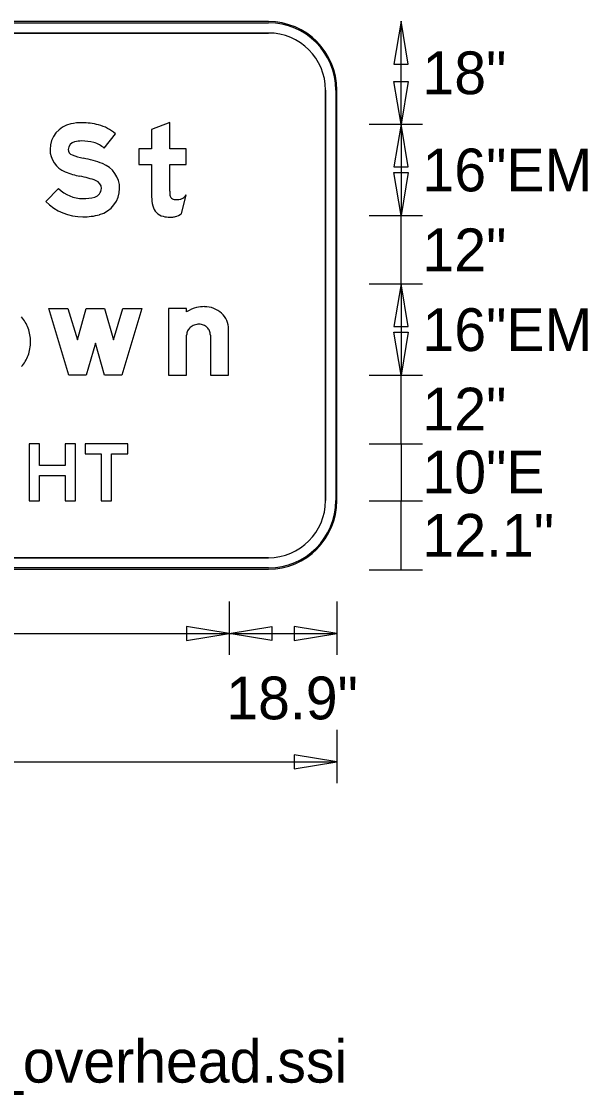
# Model space of a CAD drawing. Extents: x 1806251 to 1809821, y 414895 to 422886.
# Drawn here: x 1809677.853 to 1809678.845, y 414920.978 to 414922.862 of the extents above; entities that cross this region are included whole.
import ezdxf

# ---------------------------------------------------------------- set-up
doc = ezdxf.new("R2010")
doc.units = 0
for name, color, linetype in [('GSBWFILL', 7, 'Continuous'), ('GSCOLORFILL', 7, 'Continuous'), ('GSDIMS', 7, 'Continuous'), ('GSOUTLINE', 7, 'Continuous')]:
    doc.layers.add(name, color=color, linetype=linetype)

msp = doc.modelspace()

# ---------------------------------------------------------------- linework, layer by layer
at = {"layer": 'GSBWFILL'}
for p, q in [((1809678.286, 414922.8615), (1809676.905, 414922.8615)), ((1809676.905, 414922.8415), (1809678.286, 414922.8415)), ((1809678.386, 414922.7415), (1809678.386, 414922.0215)), ((1809678.406, 414922.0215), (1809678.406, 414922.7415)), ((1809678.1335, 414922.5246), (1809678.1419, 414922.5578)), ((1809678.1841, 414922.3118), (1809678.1841, 414922.2417)), ((1809678.286, 414921.9215), (1809676.9052, 414921.9215)), ((1809676.9052, 414921.9015), (1809678.286, 414921.9015))]:
    msp.add_line(p, q, dxfattribs=at)
for points in [[(1809678.1131, 414922.5641), (1809678.1131, 414922.6109), (1809678.1419, 414922.6109), (1809678.1419, 414922.6385), (1809678.1131, 414922.6385), (1809678.1131, 414922.6845), (1809678.0811, 414922.6723), (1809678.0811, 414922.6385), (1809678.0587, 414922.6385), (1809678.0587, 414922.6109), (1809678.0811, 414922.6109), (1809678.0811, 414922.5544)], [(1809677.9979, 414922.6394), (1809678.0177, 414922.6647)], [(1809677.918, 414922.5687), (1809677.8955, 414922.546)], [(1809678.1425, 414922.3527), (1809678.1425, 414922.3585), (1809678.1105, 414922.3585), (1809678.1105, 414922.2417), (1809678.1425, 414922.2417), (1809678.1425, 414922.3118)], [(1809678.1841, 414922.2417), (1809678.2161, 414922.2417), (1809678.2161, 414922.3224)]]:
    msp.add_lwpolyline(points, dxfattribs=at)
for points in [[(1809678.0641, 414922.3585), (1809678.0289, 414922.2417), (1809677.9985, 414922.2417), (1809677.9825, 414922.2977), (1809677.9665, 414922.2417), (1809677.9361, 414922.2417), (1809677.9009, 414922.3585), (1809677.9343, 414922.3585), (1809677.9509, 414922.3035), (1809677.9666, 414922.3585), (1809677.9984, 414922.3585), (1809678.0141, 414922.3035), (1809678.0307, 414922.3585)], [(1809677.9294, 414922.0833), (1809677.8844, 414922.0833), (1809677.8844, 414922.1213), (1809677.8664, 414922.1213), (1809677.8664, 414922.0213), (1809677.8844, 414922.0213), (1809677.8844, 414922.0653), (1809677.9294, 414922.0653), (1809677.9294, 414922.0213), (1809677.9474, 414922.0213), (1809677.9474, 414922.1213), (1809677.9294, 414922.1213)], [(1809677.9644, 414922.1033), (1809677.9929, 414922.1033), (1809677.9929, 414922.0213), (1809678.0109, 414922.0213), (1809678.0109, 414922.1033), (1809678.0394, 414922.1033), (1809678.0394, 414922.1213), (1809677.9644, 414922.1213)]]:
    msp.add_lwpolyline(points, close=True, dxfattribs=at)
for centre, radius, start, end in [((1809678.286, 414922.7415), 0.12, 0, 90), ((1809678.286, 414922.7415), 0.1, 0, 90), ((1809678.286, 414922.0215), 0.12, 270, 0), ((1809678.286, 414922.0215), 0.1, 270, 0)]:
    msp.add_arc(centre, radius, start, end, dxfattribs=at)
for centre, major_axis, ratio, start_param, end_param in [((1809677.9489, 414922.6374), (0, 0.0458), 0.999997, 0.202758, 1.570796), ((1809677.9587, 414922.5899), (0, 0.0943), 0.999997, 0, 0.202758), ((1809677.9587, 414922.5686), (0, 0.1156), 0.999997, 6.026234, 6.283185), ((1809677.9694, 414922.6094), (0, 0.0734), 0.999997, 5.565152, 6.026234), ((1809677.9489, 414922.6374), (0, 0.0138), 0.999997, 0.202758, 1.570796), ((1809677.9587, 414922.5899), (0, 0.0623), 0.999997, 0, 0.202758), ((1809677.9587, 414922.5686), (0, 0.0836), 0.999997, 6.026234, 6.283185), ((1809677.9694, 414922.6094), (0, 0.0414), 0.999997, 5.523837, 6.026234), ((1809677.9455, 414922.6374), (0, 0.0425), 0.999997, 1.570796, 2.761249), ((1809677.9455, 414922.6374), (0, 0.0105), 0.999997, 1.570796, 2.761249), ((1809677.9804, 414922.7246), (0, 0.1044), 0.999997, 2.761249, 2.95744), ((1809677.9256, 414922.4304), (0, 0.1948), 0.999997, 5.918637, 6.099033), ((1809677.9785, 414922.5689), (0, 0.0466), 0.999997, 4.712389, 5.918637), ((1809677.9804, 414922.7246), (0, 0.1364), 0.999997, 2.761249, 2.95744), ((1809677.9256, 414922.4304), (0, 0.1628), 0.999997, 5.918637, 6.099033), ((1809677.9785, 414922.5689), (0, 0.0146), 0.999997, 4.712389, 5.918637), ((1809677.9606, 414922.6117), (0, 0.0605), 0.999997, 2.360607, 3.141593), ((1809677.9775, 414922.5689), (0, 0.0155), 0.999997, 3.401517, 4.712389), ((1809677.9775, 414922.5689), (0, 0.0475), 0.999997, 3.401517, 4.712389), ((1809678.3134, 414922.5641), (0, 0.2003), 0.999998, 1.570796, 1.606005), ((1809677.9606, 414922.6117), (0, 0.0925), 0.999997, 2.360607, 3.141593), ((1809677.9606, 414922.6325), (0, 0.0814), 0.999997, 3.141593, 3.401517), ((1809678.1432, 414922.5544), (0, 0.0621), 0.999998, 1.570796, 1.830698), ((1809678.1223, 414922.5586), (0, 0.0092), 0.999998, 1.74085, 2.407828), ((1809678.1226, 414922.5589), (0, 0.00963), 0.999998, 2.407828, 3.141593), ((1809678.1226, 414922.5998), (0, 0.0505), 0.999998, 3.141593, 3.310762), ((1809678.129, 414922.5618), (0, 0.012), 0.999998, 3.310762, 3.756278), ((1809678.1208, 414922.5735), (0, 0.0263), 0.999998, 3.756278, 4.071638), ((1809678.1083, 414922.5451), (0, 0.026), 0.999998, 1.830698, 2.869526), ((1809677.9606, 414922.6325), (0, 0.1134), 0.999997, 3.141593, 3.401517), ((1809678.1131, 414922.5623), (0, 0.0438), 0.999998, 2.869526, 3.141593), ((1809678.1131, 414922.5816), (0, 0.0631), 0.999998, 3.141593, 3.205734), ((1809678.1155, 414922.5445), (0, 0.026), 0.999998, 3.205734, 3.427755), ((1809678.112, 414922.5561), (0, 0.0381), 0.999998, 3.427755, 3.738844), ((1809678.1735, 414922.3041), (0, 0.0576), 0.999997, 0.235088, 0.567132), ((1809678.174, 414922.2977), (0, 0.064), 0.999997, 0, 0.219986), ((1809678.174, 414922.3166), (0, 0.045), 0.999997, 5.914285, 6.283185), ((1809678.1751, 414922.3194), (0, 0.042), 0.999997, 5.532258, 5.914285), ((1809677.8067, 414922.3028), (0, 0.0617), 0.999994, 5.063069, 5.435798), ((1809678.1768, 414922.3212), (0, 0.0396), 0.999997, 5.130076, 5.532258), ((1809677.7993, 414922.3001), (0, 0.0696), 0.999994, 4.712389, 5.063069), ((1809678.1592, 414922.3118), (0, 0.0167), 0.999997, 1.126231, 1.570796), ((1809678.1617, 414922.3106), (0, 0.0195), 0.999997, 0.715718, 1.126231), ((1809678.1634, 414922.3087), (0, 0.022), 0.999997, 0.345704, 0.715718), ((1809678.1645, 414922.3057), (0, 0.0252), 0.999997, 0, 0.345704), ((1809678.1645, 414922.3107), (0, 0.0202), 0.999997, 5.900624, 6.283185), ((1809678.1647, 414922.3113), (0, 0.0196), 0.999997, 5.51227, 5.900624), ((1809678.165, 414922.3116), (0, 0.0191), 0.999997, 5.115435, 5.51227), ((1809678.1655, 414922.3118), (0, 0.0186), 0.999997, 4.712389, 5.115435), ((1809678.1794, 414922.3224), (0, 0.0367), 0.999997, 4.712389, 5.130076), ((1809677.7993, 414922.3001), (0, 0.0696), 0.999994, 4.361709, 4.712389), ((1809677.8067, 414922.2973), (0, 0.0617), 0.999994, 3.98898, 4.361709)]:
    msp.add_ellipse(centre, major_axis=major_axis, ratio=ratio, start_param=start_param, end_param=end_param, dxfattribs=at)
at = {"layer": 'GSCOLORFILL'}
for p, q in [((1809678.286, 414922.8615), (1809676.905, 414922.8615)), ((1809678.286, 414922.8615), (1809676.905, 414922.8615)), ((1809678.286, 414922.8615), (1809676.905, 414922.8615)), ((1809676.905, 414922.8595), (1809678.286, 414922.8595)), ((1809676.905, 414922.8415), (1809678.286, 414922.8415)), ((1809678.386, 414922.7415), (1809678.386, 414922.0215)), ((1809678.404, 414922.7415), (1809678.404, 414922.0215)), ((1809678.406, 414922.0215), (1809678.406, 414922.7415)), ((1809678.406, 414922.0215), (1809678.406, 414922.7415)), ((1809678.406, 414922.0215), (1809678.406, 414922.7415)), ((1809678.1335, 414922.5246), (1809678.1419, 414922.5578)), ((1809678.1841, 414922.3118), (1809678.1841, 414922.2417)), ((1809678.286, 414921.9215), (1809676.9052, 414921.9215)), ((1809678.286, 414921.9035), (1809676.905, 414921.9035)), ((1809676.905, 414921.9015), (1809678.286, 414921.9015)), ((1809676.905, 414921.9015), (1809678.286, 414921.9015)), ((1809676.9052, 414921.9015), (1809678.286, 414921.9015))]:
    msp.add_line(p, q, dxfattribs=at)
for points in [[(1809678.1131, 414922.5641), (1809678.1131, 414922.6109), (1809678.1419, 414922.6109), (1809678.1419, 414922.6385), (1809678.1131, 414922.6385), (1809678.1131, 414922.6845), (1809678.0811, 414922.6723), (1809678.0811, 414922.6385), (1809678.0587, 414922.6385), (1809678.0587, 414922.6109), (1809678.0811, 414922.6109), (1809678.0811, 414922.5544)], [(1809677.9979, 414922.6394), (1809678.0177, 414922.6647)], [(1809677.918, 414922.5687), (1809677.8955, 414922.546)], [(1809678.1425, 414922.3527), (1809678.1425, 414922.3585), (1809678.1105, 414922.3585), (1809678.1105, 414922.2417), (1809678.1425, 414922.2417), (1809678.1425, 414922.3118)], [(1809678.1841, 414922.2417), (1809678.2161, 414922.2417), (1809678.2161, 414922.3224)]]:
    msp.add_lwpolyline(points, dxfattribs=at)
for points in [[(1809678.0641, 414922.3585), (1809678.0289, 414922.2417), (1809677.9985, 414922.2417), (1809677.9825, 414922.2977), (1809677.9665, 414922.2417), (1809677.9361, 414922.2417), (1809677.9009, 414922.3585), (1809677.9343, 414922.3585), (1809677.9509, 414922.3035), (1809677.9666, 414922.3585), (1809677.9984, 414922.3585), (1809678.0141, 414922.3035), (1809678.0307, 414922.3585)], [(1809677.9294, 414922.0833), (1809677.8844, 414922.0833), (1809677.8844, 414922.1213), (1809677.8664, 414922.1213), (1809677.8664, 414922.0213), (1809677.8844, 414922.0213), (1809677.8844, 414922.0653), (1809677.9294, 414922.0653), (1809677.9294, 414922.0213), (1809677.9474, 414922.0213), (1809677.9474, 414922.1213), (1809677.9294, 414922.1213)], [(1809677.9644, 414922.1033), (1809677.9929, 414922.1033), (1809677.9929, 414922.0213), (1809678.0109, 414922.0213), (1809678.0109, 414922.1033), (1809678.0394, 414922.1033), (1809678.0394, 414922.1213), (1809677.9644, 414922.1213)]]:
    msp.add_lwpolyline(points, close=True, dxfattribs=at)
for centre, radius, start, end in [((1809678.286, 414922.7415), 0.12, 0, 90), ((1809678.286, 414922.7415), 0.12, 0, 90), ((1809678.286, 414922.7415), 0.12, 0, 90), ((1809678.286, 414922.7415), 0.118, 0, 90), ((1809678.286, 414922.7415), 0.1, 0, 90), ((1809678.286, 414922.0215), 0.12, 270, 0), ((1809678.286, 414922.0215), 0.12, 270, 0), ((1809678.286, 414922.0215), 0.1, 270, 0), ((1809678.286, 414922.0215), 0.12, 270, 0), ((1809678.286, 414922.0215), 0.118, 270, 0)]:
    msp.add_arc(centre, radius, start, end, dxfattribs=at)
for centre, major_axis, ratio, start_param, end_param in [((1809677.9489, 414922.6374), (0, 0.0458), 0.999997, 0.202758, 1.570796), ((1809677.9587, 414922.5899), (0, 0.0943), 0.999997, 0, 0.202758), ((1809677.9587, 414922.5686), (0, 0.1156), 0.999997, 6.026234, 6.283185), ((1809677.9694, 414922.6094), (0, 0.0734), 0.999997, 5.565152, 6.026234), ((1809677.9489, 414922.6374), (0, 0.0138), 0.999997, 0.202758, 1.570796), ((1809677.9587, 414922.5899), (0, 0.0623), 0.999997, 0, 0.202758), ((1809677.9587, 414922.5686), (0, 0.0836), 0.999997, 6.026234, 6.283185), ((1809677.9694, 414922.6094), (0, 0.0414), 0.999997, 5.523837, 6.026234), ((1809677.9455, 414922.6374), (0, 0.0425), 0.999997, 1.570796, 2.761249), ((1809677.9455, 414922.6374), (0, 0.0105), 0.999997, 1.570796, 2.761249), ((1809677.9804, 414922.7246), (0, 0.1044), 0.999997, 2.761249, 2.95744), ((1809677.9256, 414922.4304), (0, 0.1948), 0.999997, 5.918637, 6.099033), ((1809677.9785, 414922.5689), (0, 0.0466), 0.999997, 4.712389, 5.918637), ((1809677.9804, 414922.7246), (0, 0.1364), 0.999997, 2.761249, 2.95744), ((1809677.9256, 414922.4304), (0, 0.1628), 0.999997, 5.918637, 6.099033), ((1809677.9785, 414922.5689), (0, 0.0146), 0.999997, 4.712389, 5.918637), ((1809677.9606, 414922.6117), (0, 0.0605), 0.999997, 2.360607, 3.141593), ((1809677.9775, 414922.5689), (0, 0.0155), 0.999997, 3.401517, 4.712389), ((1809677.9775, 414922.5689), (0, 0.0475), 0.999997, 3.401517, 4.712389), ((1809678.3134, 414922.5641), (0, 0.2003), 0.999998, 1.570796, 1.606005), ((1809677.9606, 414922.6117), (0, 0.0925), 0.999997, 2.360607, 3.141593), ((1809677.9606, 414922.6325), (0, 0.0814), 0.999997, 3.141593, 3.401517), ((1809678.1432, 414922.5544), (0, 0.0621), 0.999998, 1.570796, 1.830698), ((1809678.1223, 414922.5586), (0, 0.0092), 0.999998, 1.74085, 2.407828), ((1809678.1226, 414922.5589), (0, 0.00963), 0.999998, 2.407828, 3.141593), ((1809678.1226, 414922.5998), (0, 0.0505), 0.999998, 3.141593, 3.310762), ((1809678.129, 414922.5618), (0, 0.012), 0.999998, 3.310762, 3.756278), ((1809678.1208, 414922.5735), (0, 0.0263), 0.999998, 3.756278, 4.071638), ((1809678.1083, 414922.5451), (0, 0.026), 0.999998, 1.830698, 2.869526), ((1809677.9606, 414922.6325), (0, 0.1134), 0.999997, 3.141593, 3.401517), ((1809678.1131, 414922.5623), (0, 0.0438), 0.999998, 2.869526, 3.141593), ((1809678.1131, 414922.5816), (0, 0.0631), 0.999998, 3.141593, 3.205734), ((1809678.1155, 414922.5445), (0, 0.026), 0.999998, 3.205734, 3.427755), ((1809678.112, 414922.5561), (0, 0.0381), 0.999998, 3.427755, 3.738844), ((1809678.1735, 414922.3041), (0, 0.0576), 0.999997, 0.235088, 0.567132), ((1809678.174, 414922.2977), (0, 0.064), 0.999997, 0, 0.219986), ((1809678.174, 414922.3166), (0, 0.045), 0.999997, 5.914285, 6.283185), ((1809678.1751, 414922.3194), (0, 0.042), 0.999997, 5.532258, 5.914285), ((1809677.8067, 414922.3028), (0, 0.0617), 0.999994, 5.063069, 5.435798), ((1809678.1768, 414922.3212), (0, 0.0396), 0.999997, 5.130076, 5.532258), ((1809677.7993, 414922.3001), (0, 0.0696), 0.999994, 4.712389, 5.063069), ((1809678.1592, 414922.3118), (0, 0.0167), 0.999997, 1.126231, 1.570796), ((1809678.1617, 414922.3106), (0, 0.0195), 0.999997, 0.715718, 1.126231), ((1809678.1634, 414922.3087), (0, 0.022), 0.999997, 0.345704, 0.715718), ((1809678.1645, 414922.3057), (0, 0.0252), 0.999997, 0, 0.345704), ((1809678.1645, 414922.3107), (0, 0.0202), 0.999997, 5.900624, 6.283185), ((1809678.1647, 414922.3113), (0, 0.0196), 0.999997, 5.51227, 5.900624), ((1809678.165, 414922.3116), (0, 0.0191), 0.999997, 5.115435, 5.51227), ((1809678.1655, 414922.3118), (0, 0.0186), 0.999997, 4.712389, 5.115435), ((1809678.1794, 414922.3224), (0, 0.0367), 0.999997, 4.712389, 5.130076), ((1809677.7993, 414922.3001), (0, 0.0696), 0.999994, 4.361709, 4.712389), ((1809677.8067, 414922.2973), (0, 0.0617), 0.999994, 3.98898, 4.361709)]:
    msp.add_ellipse(centre, major_axis=major_axis, ratio=ratio, start_param=start_param, end_param=end_param, dxfattribs=at)
at = {"layer": 'GSDIMS'}
for p, q in [((1809678.5185, 414922.6817), (1809678.5185, 414922.862)), ((1809678.4623, 414922.6817), (1809678.556, 414922.6817)), ((1809678.4623, 414922.6817), (1809678.556, 414922.6817)), ((1809678.5185, 414922.6817), (1809678.5185, 414922.5217)), ((1809678.4623, 414922.5217), (1809678.556, 414922.5217)), ((1809678.4623, 414922.5217), (1809678.556, 414922.5217)), ((1809678.5185, 414922.4017), (1809678.5185, 414922.5217)), ((1809678.4623, 414922.4017), (1809678.556, 414922.4017)), ((1809678.4623, 414922.4017), (1809678.556, 414922.4017)), ((1809678.5185, 414922.4017), (1809678.5185, 414922.2417)), ((1809678.4623, 414922.2417), (1809678.556, 414922.2417)), ((1809678.4623, 414922.2417), (1809678.556, 414922.2417)), ((1809678.5185, 414922.1213), (1809678.5185, 414922.2417)), ((1809678.4623, 414922.1213), (1809678.556, 414922.1213)), ((1809678.4623, 414922.1213), (1809678.556, 414922.1213)), ((1809678.5185, 414922.1213), (1809678.5185, 414922.0213)), ((1809678.4623, 414922.0213), (1809678.556, 414922.0213)), ((1809678.4623, 414922.0213), (1809678.556, 414922.0213)), ((1809678.5185, 414921.9003), (1809678.5185, 414922.0213)), ((1809678.4623, 414921.9003), (1809678.556, 414921.9003)), ((1809678.217, 414921.8447), (1809678.217, 414921.751)), ((1809678.217, 414921.8447), (1809678.217, 414921.751)), ((1809678.406, 414921.8447), (1809678.406, 414921.751)), ((1809676.9729, 414921.7885), (1809678.217, 414921.7885)), ((1809678.217, 414921.7885), (1809678.406, 414921.7885)), ((1809678.406, 414921.6198), (1809678.406, 414921.526)), ((1809676.785, 414921.5635), (1809678.406, 414921.5635))]:
    msp.add_line(p, q, dxfattribs=at)
for points in [[(1809678.5185, 414922.862), (1809678.506, 414922.787), (1809678.531, 414922.787)], [(1809678.5185, 414922.6817), (1809678.506, 414922.7567), (1809678.531, 414922.7567)], [(1809678.5185, 414922.6817), (1809678.506, 414922.6067), (1809678.531, 414922.6067)], [(1809678.5185, 414922.5217), (1809678.506, 414922.5967), (1809678.531, 414922.5967)], [(1809678.5185, 414922.4017), (1809678.506, 414922.3267), (1809678.531, 414922.3267)], [(1809678.5185, 414922.2417), (1809678.506, 414922.3167), (1809678.531, 414922.3167)], [(1809678.217, 414921.7885), (1809678.142, 414921.801), (1809678.142, 414921.776)], [(1809678.217, 414921.7885), (1809678.292, 414921.801), (1809678.292, 414921.776)], [(1809678.406, 414921.7885), (1809678.331, 414921.801), (1809678.331, 414921.776)], [(1809678.406, 414921.5635), (1809678.331, 414921.576), (1809678.331, 414921.551)]]:
    msp.add_lwpolyline(points, close=True, dxfattribs=at)
at = {"layer": 'GSOUTLINE'}
for p, q in [((1809678.286, 414922.8615), (1809676.905, 414922.8615)), ((1809678.286, 414922.8415), (1809676.905, 414922.8415)), ((1809678.386, 414922.0215), (1809678.386, 414922.7415)), ((1809678.406, 414922.0215), (1809678.406, 414922.7415)), ((1809678.1335, 414922.5246), (1809678.1419, 414922.5578)), ((1809678.1841, 414922.3118), (1809678.1841, 414922.2417)), ((1809676.905, 414921.9215), (1809678.286, 414921.9215)), ((1809676.905, 414921.9015), (1809678.286, 414921.9015))]:
    msp.add_line(p, q, dxfattribs=at)
for points in [[(1809678.1131, 414922.5641), (1809678.1131, 414922.6109), (1809678.1419, 414922.6109), (1809678.1419, 414922.6385), (1809678.1131, 414922.6385), (1809678.1131, 414922.6845), (1809678.0811, 414922.6723), (1809678.0811, 414922.6385), (1809678.0587, 414922.6385), (1809678.0587, 414922.6109), (1809678.0811, 414922.6109), (1809678.0811, 414922.5544)], [(1809677.9979, 414922.6394), (1809678.0177, 414922.6647)], [(1809677.918, 414922.5687), (1809677.8955, 414922.546)], [(1809678.1425, 414922.3527), (1809678.1425, 414922.3585), (1809678.1105, 414922.3585), (1809678.1105, 414922.2417), (1809678.1425, 414922.2417), (1809678.1425, 414922.3118)], [(1809678.1841, 414922.2417), (1809678.2161, 414922.2417), (1809678.2161, 414922.3224)]]:
    msp.add_lwpolyline(points, dxfattribs=at)
for points in [[(1809678.0641, 414922.3585), (1809678.0289, 414922.2417), (1809677.9985, 414922.2417), (1809677.9825, 414922.2977), (1809677.9665, 414922.2417), (1809677.9361, 414922.2417), (1809677.9009, 414922.3585), (1809677.9343, 414922.3585), (1809677.9509, 414922.3035), (1809677.9666, 414922.3585), (1809677.9984, 414922.3585), (1809678.0141, 414922.3035), (1809678.0307, 414922.3585)], [(1809677.9294, 414922.0833), (1809677.8844, 414922.0833), (1809677.8844, 414922.1213), (1809677.8664, 414922.1213), (1809677.8664, 414922.0213), (1809677.8844, 414922.0213), (1809677.8844, 414922.0653), (1809677.9294, 414922.0653), (1809677.9294, 414922.0213), (1809677.9474, 414922.0213), (1809677.9474, 414922.1213), (1809677.9294, 414922.1213)], [(1809677.9644, 414922.1033), (1809677.9929, 414922.1033), (1809677.9929, 414922.0213), (1809678.0109, 414922.0213), (1809678.0109, 414922.1033), (1809678.0394, 414922.1033), (1809678.0394, 414922.1213), (1809677.9644, 414922.1213)]]:
    msp.add_lwpolyline(points, close=True, dxfattribs=at)
for centre, radius, start, end in [((1809678.286, 414922.7415), 0.12, 0, 90), ((1809678.286, 414922.7415), 0.1, 0, 90), ((1809678.286, 414922.0215), 0.12, 270, 0), ((1809678.286, 414922.0215), 0.1, 270, 0)]:
    msp.add_arc(centre, radius, start, end, dxfattribs=at)
for centre, major_axis, ratio, start_param, end_param in [((1809677.9489, 414922.6374), (0, 0.0458), 0.999997, 0.202758, 1.570796), ((1809677.9587, 414922.5899), (0, 0.0943), 0.999997, 0, 0.202758), ((1809677.9587, 414922.5686), (0, 0.1156), 0.999997, 6.026234, 6.283185), ((1809677.9694, 414922.6094), (0, 0.0734), 0.999997, 5.565152, 6.026234), ((1809677.9489, 414922.6374), (0, 0.0138), 0.999997, 0.202758, 1.570796), ((1809677.9587, 414922.5899), (0, 0.0623), 0.999997, 0, 0.202758), ((1809677.9587, 414922.5686), (0, 0.0836), 0.999997, 6.026234, 6.283185), ((1809677.9694, 414922.6094), (0, 0.0414), 0.999997, 5.523837, 6.026234), ((1809677.9455, 414922.6374), (0, 0.0425), 0.999997, 1.570796, 2.761249), ((1809677.9455, 414922.6374), (0, 0.0105), 0.999997, 1.570796, 2.761249), ((1809677.9804, 414922.7246), (0, 0.1044), 0.999997, 2.761249, 2.95744), ((1809677.9256, 414922.4304), (0, 0.1948), 0.999997, 5.918637, 6.099033), ((1809677.9785, 414922.5689), (0, 0.0466), 0.999997, 4.712389, 5.918637), ((1809677.9804, 414922.7246), (0, 0.1364), 0.999997, 2.761249, 2.95744), ((1809677.9256, 414922.4304), (0, 0.1628), 0.999997, 5.918637, 6.099033), ((1809677.9785, 414922.5689), (0, 0.0146), 0.999997, 4.712389, 5.918637), ((1809677.9606, 414922.6117), (0, 0.0605), 0.999997, 2.360607, 3.141593), ((1809677.9775, 414922.5689), (0, 0.0155), 0.999997, 3.401517, 4.712389), ((1809677.9775, 414922.5689), (0, 0.0475), 0.999997, 3.401517, 4.712389), ((1809678.3134, 414922.5641), (0, 0.2003), 0.999998, 1.570796, 1.606005), ((1809677.9606, 414922.6117), (0, 0.0925), 0.999997, 2.360607, 3.141593), ((1809677.9606, 414922.6325), (0, 0.0814), 0.999997, 3.141593, 3.401517), ((1809678.1432, 414922.5544), (0, 0.0621), 0.999998, 1.570796, 1.830698), ((1809678.1223, 414922.5586), (0, 0.0092), 0.999998, 1.74085, 2.407828), ((1809678.1226, 414922.5589), (0, 0.00963), 0.999998, 2.407828, 3.141593), ((1809678.1226, 414922.5998), (0, 0.0505), 0.999998, 3.141593, 3.310762), ((1809678.129, 414922.5618), (0, 0.012), 0.999998, 3.310762, 3.756278), ((1809678.1208, 414922.5735), (0, 0.0263), 0.999998, 3.756278, 4.071638), ((1809678.1083, 414922.5451), (0, 0.026), 0.999998, 1.830698, 2.869526), ((1809677.9606, 414922.6325), (0, 0.1134), 0.999997, 3.141593, 3.401517), ((1809678.1131, 414922.5623), (0, 0.0438), 0.999998, 2.869526, 3.141593), ((1809678.1131, 414922.5816), (0, 0.0631), 0.999998, 3.141593, 3.205734), ((1809678.1155, 414922.5445), (0, 0.026), 0.999998, 3.205734, 3.427755), ((1809678.112, 414922.5561), (0, 0.0381), 0.999998, 3.427755, 3.738844), ((1809678.1735, 414922.3041), (0, 0.0576), 0.999997, 0.235088, 0.567132), ((1809678.174, 414922.2977), (0, 0.064), 0.999997, 0, 0.219986), ((1809678.174, 414922.3166), (0, 0.045), 0.999997, 5.914285, 6.283185), ((1809678.1751, 414922.3194), (0, 0.042), 0.999997, 5.532258, 5.914285), ((1809677.8067, 414922.3028), (0, 0.0617), 0.999994, 5.063069, 5.435798), ((1809678.1768, 414922.3212), (0, 0.0396), 0.999997, 5.130076, 5.532258), ((1809677.7993, 414922.3001), (0, 0.0696), 0.999994, 4.712389, 5.063069), ((1809678.1592, 414922.3118), (0, 0.0167), 0.999997, 1.126231, 1.570796), ((1809678.1617, 414922.3106), (0, 0.0195), 0.999997, 0.715718, 1.126231), ((1809678.1634, 414922.3087), (0, 0.022), 0.999997, 0.345704, 0.715718), ((1809678.1645, 414922.3057), (0, 0.0252), 0.999997, 0, 0.345704), ((1809678.1645, 414922.3107), (0, 0.0202), 0.999997, 5.900624, 6.283185), ((1809678.1647, 414922.3113), (0, 0.0196), 0.999997, 5.51227, 5.900624), ((1809678.165, 414922.3116), (0, 0.0191), 0.999997, 5.115435, 5.51227), ((1809678.1655, 414922.3118), (0, 0.0186), 0.999997, 4.712389, 5.115435), ((1809678.1794, 414922.3224), (0, 0.0367), 0.999997, 4.712389, 5.130076), ((1809677.7993, 414922.3001), (0, 0.0696), 0.999994, 4.361709, 4.712389), ((1809677.8067, 414922.2973), (0, 0.0617), 0.999994, 3.98898, 4.361709)]:
    msp.add_ellipse(centre, major_axis=major_axis, ratio=ratio, start_param=start_param, end_param=end_param, dxfattribs=at)

# ---------------------------------------------------------------- texts
at = {"layer": 'GSDIMS'}
for s, p in [('18"', (1809678.556, 414922.7342)), ('16"EM', (1809678.556, 414922.5638)), ('12"', (1809678.556, 414922.4238)), ('16"EM', (1809678.556, 414922.2838)), ('12"', (1809678.556, 414922.1445)), ('10"E', (1809678.556, 414922.0342)), ('12.1"', (1809678.556, 414921.9232)), ('18.9"', (1809678.212, 414921.638)), ('Panel Style: guide_fwy_overhead.ssi', (1809676.785, 414921.001))]:
    msp.add_text(s, height=0.075, dxfattribs=at).set_placement(p)

doc.saveas('drawing.dxf')
